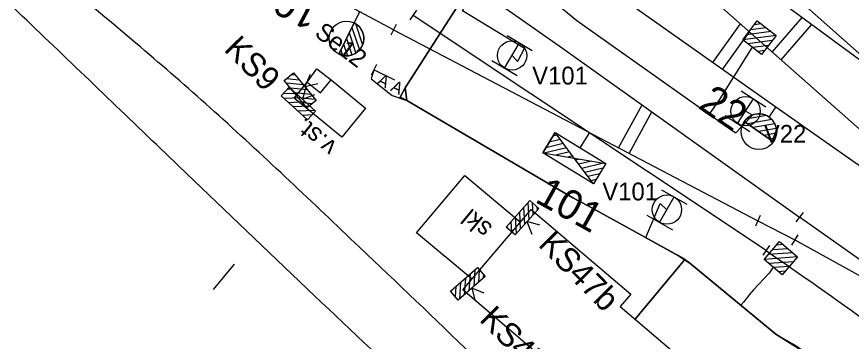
# Model space of a CAD drawing. Extents: x -496570 to -495506, y -1089156 to -1088046.
# Drawn here: x -496069.2 to -495999, y -1088619.5 to -1088592.2 of the extents above; entities that cross this region are included whole.
import ezdxf

# ---------------------------------------------------------------- set-up
doc = ezdxf.new("R2010")
doc.units = 0
for name, color, linetype in [('11', 7, 'Continuous'), ('14', 7, 'Continuous'), ('15', 7, 'Continuous'), ('20', 7, 'Continuous'), ('27', 7, 'Continuous'), ('39', 7, 'Continuous'), ('54', 7, 'Continuous'), ('PŘÍSTUPOVÉ_CESTY', 7, 'Continuous'), ('PŮVODNÍ_NÁVRH', 7, 'Continuous'), ('SEE', 7, 'Continuous')]:
    doc.layers.add(name, color=color, linetype=linetype)

msp = doc.modelspace()

# ---------------------------------------------------------------- linework, layer by layer
at = {"layer": '11'}
for points in [[(-496010.65, -1088596.039), (-496008.311, -1088592.783)], [(-496005.636, -1088595.169), (-496003.123, -1088592.245)], [(-496004.878, -1088595.821), (-496002.34, -1088592.868)], [(-496009.838, -1088596.623), (-496007.566, -1088593.459)], [(-496018.569, -1088603.2), (-496016.588, -1088599.594)], [(-496017.693, -1088603.682), (-496015.773, -1088600.186)]]:
    msp.add_lwpolyline(points, dxfattribs=at)
at = {"layer": '14'}
for p, q in [((-495993.785, -1088605.649), (-496022.225, -1088580.492)), ((-495994.931, -1088607.083), (-496005.328, -1088599.803)), ((-496006.851, -1088609.348), (-496003.75, -1088610.956))]:
    msp.add_line(p, q, dxfattribs=at)
for points in [[(-496063.029, -1088566.985), (-496037.138, -1088585.134), (-496023.296, -1088594.829), (-496003.341, -1088609.037)], [(-496037.513, -1088593.285), (-496040.369, -1088591.776), (-496048.068, -1088587.699), (-496063.641, -1088579.453)], [(-496044.162, -1088615.65), (-496055.593, -1088604.743)]]:
    msp.add_lwpolyline(points, dxfattribs=at)
for points in [[(-496009.526, -1088642.986), (-496015.368, -1088636.526), (-496021.579, -1088629.917), (-496040.398, -1088611.545), (-496052.231, -1088600.497), (-496064.07, -1088590.377), (-496077.737, -1088579.829), (-496084.463, -1088574.911)], [(-496055.593, -1088604.743), (-496067.647, -1088593.203), (-496079.673, -1088581.848), (-496085.454, -1088576.574)], [(-495939.964, -1088690.857), (-495942.044, -1088686.532), (-495949.093, -1088672.316), (-495953.81, -1088663.645), (-495962.754, -1088650.285), (-495972.743, -1088638.936), (-495985.077, -1088627.584), (-495997.355, -1088618.062), (-496006.199, -1088611.844)], [(-496010.937, -1088644.43), (-496017.591, -1088639.193), (-496024.853, -1088633.259), (-496044.162, -1088615.65)]]:
    msp.add_spline(points, degree=3, dxfattribs=at)
at = {"layer": '15'}
for p, q in [((-496006.58, -1088592.794), (-496007.154, -1088592.869)), ((-496005.739, -1088593.44), (-496007.8, -1088593.71)), ((-496006.16, -1088593.117), (-496007.477, -1088593.289)), ((-496027.965, -1088593.76), (-496025.85, -1088595.025)), ((-496005.319, -1088593.763), (-496008.123, -1088594.131)), ((-496005.641, -1088594.184), (-496007.703, -1088594.454)), ((-496028.172, -1088596.507), (-496026.908, -1088594.393)), ((-496005.965, -1088594.605), (-496007.282, -1088594.777)), ((-496006.288, -1088595.025), (-496006.861, -1088595.1)), ((-496029.23, -1088595.875), (-496027.115, -1088597.14)), ((-496008.247, -1088598.426), (-496006.184, -1088599.773)), ((-496008.562, -1088601.163), (-496007.216, -1088599.099)), ((-496009.594, -1088600.489), (-496007.531, -1088601.836)), ((-496014.972, -1088606.73), (-496012.83, -1088607.948)), ((-496015.119, -1088609.481), (-496013.901, -1088607.339)), ((-496016.19, -1088608.872), (-496014.048, -1088610.09)), ((-496004.305, -1088611.69), (-496005.629, -1088611.783)), ((-496004.705, -1088611.342), (-496005.282, -1088611.383)), ((-496003.504, -1088612.386), (-496006.325, -1088612.584)), ((-496003.904, -1088612.038), (-496005.977, -1088612.184)), ((-496003.851, -1088612.786), (-496005.925, -1088612.932)), ((-496004.199, -1088613.187), (-496005.524, -1088613.28)), ((-496004.547, -1088613.587), (-496005.124, -1088613.628))]:
    msp.add_line(p, q, dxfattribs=at)
for points in [[(-496006.537, -1088595.349), (-496008.123, -1088594.131), (-496006.904, -1088592.545), (-496005.319, -1088593.763)], [(-496006.537, -1088595.349), (-496008.123, -1088594.131), (-496006.904, -1088592.545), (-496005.319, -1088593.763)], [(-496004.815, -1088613.896), (-496006.325, -1088612.584), (-496005.014, -1088611.074), (-496003.504, -1088612.386)], [(-496004.815, -1088613.896), (-496006.325, -1088612.584), (-496005.014, -1088611.074), (-496003.504, -1088612.386)]]:
    msp.add_lwpolyline(points, close=True, dxfattribs=at)
for points in [[(-496006.537, -1088595.349), (-496008.123, -1088594.131), (-496006.904, -1088592.545), (-496005.319, -1088593.763), (-496006.537, -1088595.349)], [(-496006.537, -1088595.349), (-496008.123, -1088594.131), (-496006.904, -1088592.545), (-496005.319, -1088593.763), (-496006.537, -1088595.349)], [(-496004.815, -1088613.896), (-496006.325, -1088612.584), (-496005.014, -1088611.074), (-496003.504, -1088612.386), (-496004.815, -1088613.896)], [(-496004.815, -1088613.896), (-496006.325, -1088612.584), (-496005.014, -1088611.074), (-496003.504, -1088612.386), (-496004.815, -1088613.896)]]:
    msp.add_lwpolyline(points, dxfattribs=at)
for centre in [(-496027.539, -1088595.445), (-496007.887, -1088600.126), (-496014.509, -1088608.405)]:
    msp.add_circle(centre, 1.232, dxfattribs=at)
at = {"layer": '20'}
for p, q in [((-496038.964, -1088596.199), (-496039.396, -1088597.101)), ((-496037.395, -1088597.506), (-496039.18, -1088596.65))]:
    msp.add_line(p, q, dxfattribs=at)
at = {"layer": '27'}
for p, q in [((-496040.828, -1088592.696), (-496040.369, -1088591.776)), ((-496035.576, -1088591.63), (-496036.138, -1088592.456)), ((-496040.828, -1088592.697), (-496042.124, -1088595.321)), ((-496042.124, -1088595.321), (-496040.827, -1088592.697)), ((-496040.827, -1088592.697), (-496040.828, -1088592.697)), ((-496040.73, -1088592.755), (-496040.121, -1088594.552)), ((-496037.286, -1088592.84), (-496037.74, -1088593.73)), ((-496041.251, -1088593.553), (-496040.682, -1088595.236)), ((-496041.016, -1088593.078), (-496040.376, -1088594.971)), ((-496041.486, -1088594.03), (-496041.023, -1088595.397)), ((-496041.956, -1088594.981), (-496041.803, -1088595.432)), ((-496041.721, -1088594.504), (-496041.395, -1088595.466)), ((-496005.903, -1088600.621), (-496005.328, -1088599.803)), ((-496006.116, -1088600.498), (-496007.831, -1088600.798)), ((-496007.993, -1088600.986), (-496005.538, -1088602.711)), ((-496005.538, -1088602.711), (-496007.993, -1088600.986)), ((-496005.672, -1088600.826), (-496007.712, -1088601.184)), ((-496005.422, -1088601.189), (-496007.25, -1088601.508)), ((-496021.794, -1088603.22), (-496021.003, -1088601.932)), ((-496005.294, -1088601.573), (-496006.786, -1088601.834)), ((-496005.274, -1088601.976), (-496006.323, -1088602.159)), ((-496023.492, -1088602.5), (-496024.411, -1088602.722)), ((-496023.753, -1088602.151), (-496024.117, -1088602.24)), ((-496005.374, -1088602.399), (-496005.861, -1088602.484)), ((-496022.97, -1088603.196), (-496024.844, -1088603.652)), ((-496023.231, -1088602.847), (-496024.705, -1088603.206)), ((-496022.708, -1088603.543), (-496023.843, -1088603.82)), ((-496022.447, -1088603.892), (-496022.842, -1088603.988)), ((-496021.846, -1088604.155), (-496022.188, -1088604.238)), ((-496020.844, -1088604.322), (-496021.926, -1088604.586)), ((-496019.842, -1088604.491), (-496021.665, -1088604.934)), ((-496019.892, -1088604.915), (-496021.405, -1088605.283)), ((-496020.185, -1088605.397), (-496021.143, -1088605.63)), ((-496020.48, -1088605.881), (-496020.882, -1088605.979)), ((-496006.646, -1088608.892), (-496007.056, -1088609.804)), ((-496003.038, -1088608.639), (-496003.644, -1088609.435)), ((-496003.486, -1088610.531), (-496004.014, -1088611.381)), ((-496003.75, -1088610.956), (-495989.792, -1088618.606)), ((-496005.864, -1088611.409), (-496006.434, -1088612.231))]:
    msp.add_line(p, q, dxfattribs=at)
for points in [[(-496005.328, -1088599.803), (-496018.9, -1088590.217), (-496031.561, -1088580.038)], [(-495984.692, -1088607.313), (-495994.886, -1088598.298), (-496009.888, -1088585.031)], [(-495994.886, -1088598.298), (-496011.01, -1088586.449)], [(-496035.857, -1088592.043), (-496006.149, -1088611.82)], [(-496037.513, -1088593.285), (-496006.851, -1088609.348)], [(-496024.964, -1088603.631), (-496022.309, -1088604.077), (-496023.924, -1088601.923), (-496024.964, -1088603.631)], [(-496020.693, -1088606.231), (-496022.309, -1088604.077), (-496019.653, -1088604.523), (-496020.693, -1088606.231)], [(-495981.197, -1088624.677), (-495989.792, -1088618.606), (-496003.341, -1088609.037)]]:
    msp.add_lwpolyline(points, dxfattribs=at)
msp.add_lwpolyline([(-496020.693, -1088606.231), (-496024.964, -1088603.631), (-496023.924, -1088601.923), (-496019.653, -1088604.523)], close=True, dxfattribs=at)
for centre, radius in [((-496041.478, -1088594.017), 1.462), ((-496006.765, -1088601.849), 1.5)]:
    msp.add_circle(centre, radius, dxfattribs=at)
for centre, radius, start, end in [((-496041.476, -1088594.009), 1.464, 243.7017, 63.66255), ((-496006.765, -1088601.849), 1.5, 324.91006, 144.91006)]:
    msp.add_arc(centre, radius, start, end, dxfattribs=at)
at = {"layer": '39'}
for points in [[(-496044.777, -1088597.689), (-496043.961, -1088596.558), (-496042.779, -1088597.501)], [(-496041.881, -1088602.309), (-496045.876, -1088599.025), (-496044.777, -1088597.689), (-496043.666, -1088598.584), (-496042.779, -1088597.501), (-496039.885, -1088599.872), (-496041.881, -1088602.309)], [(-496030.9, -1088614.237), (-496035.577, -1088610.363), (-496031.519, -1088605.544), (-496026.842, -1088609.462)], [(-496025.935, -1088608.395), (-496017.554, -1088615.508), (-496018.431, -1088616.535), (-496006.552, -1088626.674), (-496012.512, -1088633.736), (-496023.309, -1088624.531), (-496022.209, -1088623.243), (-496031.678, -1088615.152), (-496025.935, -1088608.395)]]:
    msp.add_lwpolyline(points, dxfattribs=at)
at = {"layer": '54'}
for points in [[(-496017.181, -1088617.602), (-496012.99, -1088612.61), (-496021.18, -1088608.07), (-496022.438, -1088607.407), (-496036.409, -1088599.224), (-496036.551, -1088598.154), (-496029.489, -1088587.165), (-496028.39, -1088586.02), (-496017.71, -1088569.84), (-496015.829, -1088567.72), (-496024.83, -1088557.73), (-496035.05, -1088546.1), (-496051.01, -1088524.68)], [(-495936.743, -1088670.436), (-495952.112, -1088656.757), (-495966.13, -1088641.736), (-495969.086, -1088638.597), (-495972.985, -1088642.454), (-495974.115, -1088643.402), (-495977.11, -1088640.04), (-495990.27, -1088628.8), (-496002.7, -1088620.53), (-496005.33, -1088618.88), (-496012.58, -1088612.9), (-496012.99, -1088612.61), (-496013.61, -1088612.22), (-496021.18, -1088608.07), (-496022.438, -1088607.407), (-496036.409, -1088599.224), (-496036.551, -1088598.154), (-496029.489, -1088587.165), (-496028.39, -1088586.02), (-496017.71, -1088569.84), (-496015.829, -1088567.72), (-496024.83, -1088557.73), (-496035.05, -1088546.1), (-496051.31, -1088524.79)], [(-496051.31, -1088524.79), (-496034.93, -1088546.87), (-496024.83, -1088557.73), (-496015.783, -1088567.718), (-496017.71, -1088569.84), (-496028.39, -1088586.02), (-496029.489, -1088587.165), (-496036.551, -1088598.154), (-496036.409, -1088599.224), (-496022.438, -1088607.407), (-496021.18, -1088608.07), (-496013.61, -1088612.22), (-496012.58, -1088612.9), (-496008.281, -1088616.445), (-496005.33, -1088618.88), (-496003.57, -1088619.88), (-496002.7, -1088620.53), (-495990.27, -1088628.8), (-495988.28, -1088630.5), (-495980.92, -1088636.9), (-495977.11, -1088640.04), (-495974.115, -1088643.402)], [(-496027.54, -1088595.45), (-496027.07, -1088595.95), (-496026.97, -1088595.75), (-496026.49, -1088594.86), (-496031.7, -1088591.7), (-496029.151, -1088586.587)], [(-496029.151, -1088586.587), (-496028.657, -1088586.958), (-496026.671, -1088588.724), (-496022.09, -1088592.506), (-496010.962, -1088600.371), (-496008.713, -1088601.961), (-496007.3, -1088600.45), (-496007.889, -1088600.131)], [(-496007.33, -1088594.74), (-496010.11, -1088599.17), (-496010.962, -1088600.371)], [(-496039.18, -1088596.65), (-496039.4, -1088597.41), (-496037.62, -1088598.82), (-496036.409, -1088599.224)], [(-496016.29, -1088610.74), (-496015.08, -1088607.89), (-496014.51, -1088608.41)], [(-496005.57, -1088613.24), (-496005.91, -1088613.75), (-496007.21, -1088615.15), (-496007.37, -1088615.32), (-496007.43, -1088615.41), (-496008.05, -1088616.19), (-496008.281, -1088616.445)]]:
    msp.add_lwpolyline(points, dxfattribs=at)
at = {"layer": 'PŘÍSTUPOVÉ_CESTY'}
for p, q in [((-496046.106, -1088597.038), (-496045.799, -1088597.068)), ((-496046.533, -1088597.75), (-496045.126, -1088597.888)), ((-496046.516, -1088597.374), (-496045.463, -1088597.478)), ((-496046.438, -1088598.262), (-496046.13, -1088598.248)), ((-496046.197, -1088598.159), (-496044.79, -1088598.297)), ((-496046.795, -1088598.654), (-496045.738, -1088598.606)), ((-496046.759, -1088599.028), (-496045.346, -1088598.964)), ((-496045.861, -1088598.569), (-496044.453, -1088598.707)), ((-496045.523, -1088598.979), (-496044.116, -1088599.117)), ((-496046.367, -1088599.385), (-496044.955, -1088599.321)), ((-496045.976, -1088599.743), (-496044.563, -1088599.678)), ((-496045.187, -1088599.389), (-496044.343, -1088599.472)), ((-496044.851, -1088599.798), (-496044.752, -1088599.808)), ((-496045.584, -1088600.101), (-496044.171, -1088600.036)), ((-496045.192, -1088600.458), (-496044.345, -1088600.419)), ((-496044.801, -1088600.815), (-496044.702, -1088600.811)), ((-496026.572, -1088608.233), (-496026.493, -1088609.645)), ((-496026.218, -1088607.838), (-496026.14, -1088609.25)), ((-496025.845, -1088607.798), (-496025.786, -1088608.854)), ((-496025.45, -1088608.151), (-496025.433, -1088608.459)), ((-496027.279, -1088609.023), (-496027.201, -1088610.435)), ((-496026.925, -1088608.628), (-496026.847, -1088610.04)), ((-496027.633, -1088609.418), (-496027.586, -1088610.266)), ((-496027.986, -1088609.813), (-496027.981, -1088609.912)), ((-496031.073, -1088613.809), (-496031.168, -1088615.22)), ((-496030.674, -1088613.46), (-496030.769, -1088614.871)), ((-496030.298, -1088613.466), (-496030.369, -1088614.522)), ((-496029.949, -1088613.865), (-496029.97, -1088614.173)), ((-496031.872, -1088614.507), (-496031.967, -1088615.918)), ((-496031.472, -1088614.158), (-496031.567, -1088615.569)), ((-496032.67, -1088615.205), (-496032.676, -1088615.303)), ((-496032.271, -1088614.856), (-496032.328, -1088615.702))]:
    msp.add_line(p, q, dxfattribs=at)
for points in [[(-496045.938, -1088596.9), (-496044.033, -1088599.218), (-496044.806, -1088599.852), (-496046.711, -1088597.534)], [(-496046.291, -1088598.101), (-496044.075, -1088600.124), (-496044.749, -1088600.863), (-496046.965, -1088598.84)], [(-496025.287, -1088608.297), (-496027.288, -1088610.532), (-496028.033, -1088609.865), (-496026.032, -1088607.63)], [(-496029.806, -1088614.029), (-496032.064, -1088616.004), (-496032.722, -1088615.251), (-496030.464, -1088613.276)]]:
    msp.add_lwpolyline(points, close=True, dxfattribs=at)
for points in [[(-496045.938, -1088596.9), (-496044.033, -1088599.218), (-496044.806, -1088599.852), (-496046.711, -1088597.534), (-496045.938, -1088596.9)], [(-496044.53, -1088597.037), (-496044.986, -1088598.059), (-496043.896, -1088597.81)], [(-496046.291, -1088598.101), (-496044.075, -1088600.124), (-496044.749, -1088600.863), (-496046.965, -1088598.84), (-496046.291, -1088598.101)], [(-496044.878, -1088598.037), (-496045.183, -1088599.113), (-496044.139, -1088598.711)], [(-496025.287, -1088608.297), (-496027.288, -1088610.532), (-496028.033, -1088609.865), (-496026.032, -1088607.63), (-496025.287, -1088608.297)], [(-496025.209, -1088609.709), (-496026.287, -1088609.414), (-496025.876, -1088610.454)], [(-496029.806, -1088614.029), (-496032.064, -1088616.004), (-496032.722, -1088615.251), (-496030.464, -1088613.276), (-496029.806, -1088614.029)], [(-496029.9, -1088615.44), (-496030.935, -1088615.016), (-496030.653, -1088616.098)]]:
    msp.add_lwpolyline(points, dxfattribs=at)
at = {"layer": 'PŮVODNÍ_NÁVRH'}
msp.add_line((-496052.686, -1088615.118), (-496050.904, -1088612.982), dxfattribs=at)
msp.add_lwpolyline([(-495974.115, -1088643.402), (-495977.11, -1088640.04), (-495980.92, -1088636.9), (-495990.27, -1088628.8), (-496002.7, -1088620.53), (-496005.33, -1088618.88), (-496012.58, -1088612.9), (-496013.61, -1088612.22), (-496021.18, -1088608.07), (-496022.438, -1088607.407), (-496036.409, -1088599.224), (-496036.952, -1088598.948), (-496036.551, -1088598.154), (-496029.489, -1088587.165), (-496028.39, -1088586.02), (-496017.71, -1088569.84), (-496015.829, -1088567.72)], dxfattribs=at)
at = {"layer": 'SEE'}
msp.add_line((-496012.99, -1088612.61), (-496017.181, -1088617.602), dxfattribs=at)
for points in [[(-496051.31, -1088524.79), (-496034.93, -1088546.87), (-496024.83, -1088557.73), (-496015.829, -1088567.72), (-496017.71, -1088569.84), (-496028.39, -1088586.02), (-496029.489, -1088587.165), (-496036.551, -1088598.154), (-496036.952, -1088598.948), (-496036.409, -1088599.224), (-496022.438, -1088607.407), (-496021.18, -1088608.07), (-496013.61, -1088612.22), (-496012.58, -1088612.9), (-496005.33, -1088618.88), (-496002.7, -1088620.53), (-495990.27, -1088628.8), (-495980.92, -1088636.9), (-495977.11, -1088640.04), (-495975.448, -1088642.109)], [(-496051.31, -1088524.79), (-496034.93, -1088546.87), (-496024.83, -1088557.73), (-496015.829, -1088567.72), (-496017.71, -1088569.84), (-496028.39, -1088586.02), (-496029.489, -1088587.165), (-496036.551, -1088598.154), (-496036.952, -1088598.948), (-496036.409, -1088599.224), (-496022.438, -1088607.407), (-496021.18, -1088608.07), (-496013.61, -1088612.22), (-496012.58, -1088612.9), (-496005.33, -1088618.88), (-496002.7, -1088620.53), (-495990.27, -1088628.8), (-495980.92, -1088636.9), (-495977.11, -1088640.04), (-495974.115, -1088643.402)]]:
    msp.add_lwpolyline(points, dxfattribs=at)

# ---------------------------------------------------------------- texts
at = {"layer": '15'}
for s, p in [('V101', (-496025.846, -1088597.884)), ('V22', (-496006.342, -1088602.783)), ('V101', (-496019.944, -1088607.631))]:
    msp.add_text(s, height=1.5, dxfattribs=at).set_placement(p)
at = {"layer": '20'}
for s, height, rotation, p in [('Se12', 1.5, 323.04383, (-496044.257, -1088593.739)), ('  A A', 1, 334.37723, (-496039.64, -1088597.51))]:
    msp.add_text(s, height=height, rotation=rotation, dxfattribs=at).set_placement(p)
at = {"layer": '27'}
for s, rotation, p in [('102', 152.09658, (-496043.438, -1088591.242)), ('22', 325.69775, (-496011.961, -1088599.818)), ('101', 331.0399, (-496025.709, -1088607.719))]:
    msp.add_text(s, height=2.5, rotation=rotation, dxfattribs=at).set_placement(p)
at = {"layer": '39'}
for s, rotation, p in [('v.st.', 140.57885, (-496042.186, -1088602.907)), ('skl', 140.36475, (-496029.108, -1088609.801))]:
    msp.add_text(s, height=1.5, rotation=rotation, dxfattribs=at).set_placement(p)
at = {"layer": 'PŘÍSTUPOVÉ_CESTY'}
for s, p in [('KS9', (-496051.871, -1088595)), ('KS47b', (-496025.416, -1088611.414)), ('KS47a', (-496030.374, -1088617.715))]:
    msp.add_text(s, height=2, rotation=314.76049, dxfattribs=at).set_placement(p)

doc.saveas('drawing.dxf')
